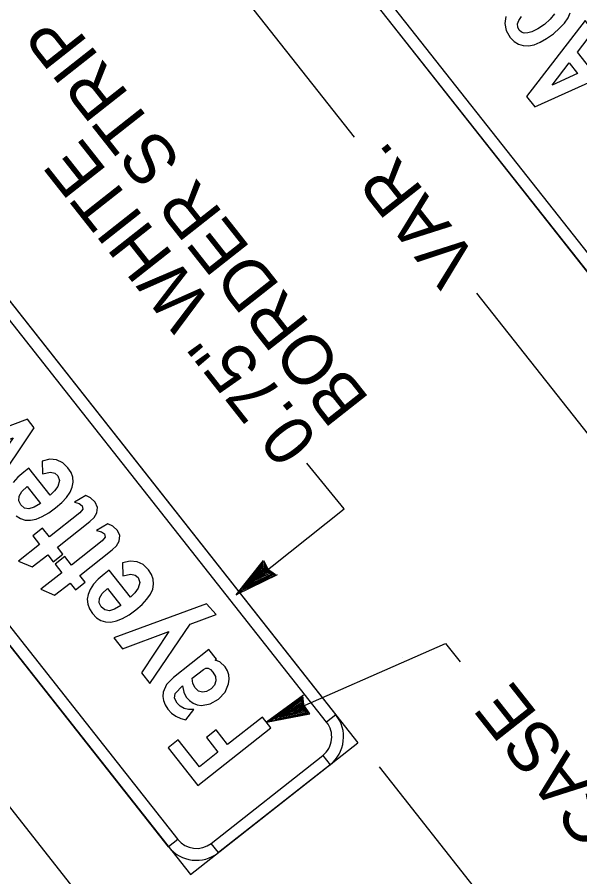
# Model space of a CAD drawing. Extents: x 672126 to 673696, y 1673540 to 1674900.
# Drawn here: x 672259.8 to 672307.3, y 1674609.9 to 1674682.5 of the extents above; entities that cross this region are included whole.
import ezdxf

# ---------------------------------------------------------------- set-up
doc = ezdxf.new("R2010")
doc.units = 0
for name, color, linetype in [('C-ANNO-SYMB', 7, 'Continuous'), ('Level 1', 7, 'Continuous'), ('V-SIGNAL-LOOP', 7, 'Continuous')]:
    doc.layers.add(name, color=color, linetype=linetype)

msp = doc.modelspace()

# ---------------------------------------------------------------- linework, layer by layer
at = {"layer": 'C-ANNO-SYMB'}
for p, q in [((672275.262, 1674702.456), (672319.838, 1674645.914)), ((672247.706, 1674673.092), (672288.567, 1674621.261)), ((672233.571, 1674661.948), (672274.431, 1674610.117)), ((672286.71, 1674623.617), (672285.924, 1674622.998)), ((672274.431, 1674610.117), (672288.567, 1674621.261)), ((672285.592, 1674620.189), (672286.211, 1674619.404)), ((672273.359, 1674613.092), (672272.574, 1674612.473)), ((672276.787, 1674611.975), (672276.168, 1674612.76))]:
    msp.add_line(p, q, dxfattribs=at)
for points in [[(672277.905, 1674700.719), (672318.766, 1674648.889), (672317.98, 1674648.27), (672277.12, 1674700.1), (672277.905, 1674700.719), (672277.905, 1674700.719)], [(672285.924, 1674622.998), (672248.778, 1674670.117), (672249.564, 1674670.736), (672286.71, 1674623.617), (672285.924, 1674622.998), (672285.924, 1674622.998)], [(672236.213, 1674660.211), (672273.359, 1674613.092), (672272.574, 1674612.473), (672235.428, 1674659.592), (672236.213, 1674660.211), (672236.213, 1674660.211)], [(672257.802, 1674642.767), (672261.237, 1674647.852), (672260.664, 1674648.579), (672254.912, 1674646.433), (672255.696, 1674645.551), (672259.462, 1674647.025), (672257.166, 1674643.686)], [(672264.626, 1674641.585), (672265.042, 1674641.455), (672265.278, 1674641.283), (672265.345, 1674640.996), (672265.1, 1674640.689), (672262.516, 1674638.652), (672261.937, 1674639.386), (672261.117, 1674638.74), (672261.696, 1674638.006), (672259.918, 1674636.604), (672261.08, 1674636.109), (672262.382, 1674637.136), (672262.842, 1674636.553), (672263.662, 1674637.199), (672263.202, 1674637.782), (672265.933, 1674639.935), (672266.301, 1674640.292), (672266.526, 1674640.675), (672266.582, 1674641.142), (672266.385, 1674641.57), (672266.004, 1674641.941), (672265.584, 1674642.13)], [(672266.508, 1674639.198), (672266.924, 1674639.067), (672267.16, 1674638.895), (672267.227, 1674638.609), (672266.982, 1674638.302), (672264.398, 1674636.265), (672263.819, 1674636.999), (672263, 1674636.353), (672263.578, 1674635.619), (672261.8, 1674634.217), (672262.962, 1674633.722), (672264.264, 1674634.748), (672264.724, 1674634.165), (672265.544, 1674634.812), (672265.084, 1674635.394), (672267.815, 1674637.547), (672268.183, 1674637.904), (672268.408, 1674638.287), (672268.464, 1674638.754), (672268.267, 1674639.183), (672267.886, 1674639.553), (672267.466, 1674639.743)], [(672276.595, 1674632.098), (672275.794, 1674632.989), (672267.961, 1674630.13), (672268.701, 1674629.191), (672272.617, 1674630.656), (672270.294, 1674627.171), (672270.999, 1674626.277), (672274.405, 1674631.287)], [(672281.214, 1674622.512), (672280.498, 1674623.42), (672277.564, 1674621.108), (672276.59, 1674622.344), (672275.778, 1674621.705), (672276.753, 1674620.468), (672275.182, 1674619.23), (672273.4, 1674621.491), (672272.554, 1674620.824), (672275.052, 1674617.655)], [(672276.168, 1674612.76), (672285.592, 1674620.189), (672286.211, 1674619.404), (672276.787, 1674611.975), (672276.168, 1674612.76), (672276.168, 1674612.76)]]:
    msp.add_lwpolyline(points, close=True, dxfattribs=at)
for points in [[(672301.055, 1674682.604), (672300.962, 1674682.007), (672301.088, 1674681.405), (672301.42, 1674680.832), (672301.751, 1674680.489), (672302.116, 1674680.26), (672302.519, 1674680.137), (672302.955, 1674680.123), (672303.432, 1674680.217), (672303.94, 1674680.419), (672304.487, 1674680.731), (672305.069, 1674681.15), (672305.591, 1674681.602), (672306.002, 1674682.045), (672306.303, 1674682.481), (672306.489, 1674682.909)], [(672305.163, 1674682.816), (672304.8, 1674682.376), (672304.305, 1674681.937), (672303.764, 1674681.563), (672303.245, 1674681.312), (672302.903, 1674681.211), (672302.61, 1674681.198), (672302.373, 1674681.27), (672302.183, 1674681.433), (672302.05, 1674681.69), (672302.037, 1674681.967), (672302.146, 1674682.268), (672302.371, 1674682.588)], [(672310.87, 1674678.287), (672310.165, 1674679.181), (672308.14, 1674678.261), (672307.092, 1674679.59), (672308.445, 1674681.364), (672307.735, 1674682.264), (672302.798, 1674675.853), (672303.485, 1674674.983), (672310.87, 1674678.287)], [(672307.092, 1674677.787), (672304.96, 1674676.811), (672306.387, 1674678.682), (672307.092, 1674677.787)], [(672259.709, 1674640.431), (672260.076, 1674640.197), (672260.481, 1674640.072), (672260.919, 1674640.059), (672261.399, 1674640.154), (672261.911, 1674640.358), (672262.46, 1674640.672), (672263.046, 1674641.094), (672263.564, 1674641.542), (672263.972, 1674641.983), (672264.27, 1674642.418), (672264.454, 1674642.844), (672264.532, 1674643.263), (672264.495, 1674643.677), (672264.348, 1674644.085), (672264.088, 1674644.483), (672263.643, 1674644.912), (672263.132, 1674645.15), (672262.556, 1674645.198), (672261.91, 1674645.053), (672261.947, 1674643.973), (672262.621, 1674644.102), (672262.977, 1674644.029), (672263.243, 1674643.817), (672263.38, 1674643.414), (672263.224, 1674642.914), (672262.957, 1674642.53), (672262.589, 1674642.163)], [(672262.589, 1674642.163), (672260.785, 1674644.45), (672260.36, 1674644.115), (672259.86, 1674643.679), (672259.463, 1674643.246)], [(672261.762, 1674641.471), (672261.245, 1674641.149), (672260.795, 1674641.021), (672260.414, 1674641.085), (672260.102, 1674641.341), (672259.934, 1674641.694), (672259.965, 1674642.075), (672260.2, 1674642.474), (672260.636, 1674642.9), (672261.762, 1674641.471)], [(672269.374, 1674633.555), (672267.571, 1674635.843), (672267.146, 1674635.508), (672266.646, 1674635.072), (672266.248, 1674634.639), (672265.963, 1674634.213), (672265.784, 1674633.793), (672265.717, 1674633.376), (672265.756, 1674632.965), (672265.907, 1674632.561), (672266.161, 1674632.164), (672266.494, 1674631.823), (672266.861, 1674631.589), (672267.267, 1674631.465), (672267.705, 1674631.452), (672268.185, 1674631.547), (672268.696, 1674631.751), (672269.245, 1674632.065), (672269.831, 1674632.487), (672270.349, 1674632.935), (672270.758, 1674633.376), (672271.056, 1674633.811), (672271.24, 1674634.237), (672271.317, 1674634.656), (672271.28, 1674635.07), (672271.133, 1674635.478), (672270.873, 1674635.876), (672270.428, 1674636.305), (672269.918, 1674636.543), (672269.341, 1674636.591), (672268.696, 1674636.446), (672268.733, 1674635.366), (672269.406, 1674635.495), (672269.763, 1674635.422), (672270.028, 1674635.21), (672270.166, 1674634.807), (672270.009, 1674634.307), (672269.742, 1674633.923), (672269.374, 1674633.555)], [(672268.548, 1674632.864), (672268.03, 1674632.542), (672267.581, 1674632.414), (672267.2, 1674632.478), (672266.887, 1674632.734), (672266.719, 1674633.087), (672266.75, 1674633.468), (672266.986, 1674633.867), (672267.421, 1674634.293), (672268.548, 1674632.864)], [(672276.627, 1674628.33), (672275.99, 1674629.139), (672272.99, 1674626.774), (672272.412, 1674626.18), (672272.115, 1674625.539), (672272.084, 1674625.174), (672272.14, 1674624.814), (672272.287, 1674624.452), (672272.521, 1674624.096), (672272.842, 1674623.755), (672273.203, 1674623.492), (672273.608, 1674623.305), (672274.049, 1674623.194), (672274.704, 1674624.072), (672274.275, 1674624.074), (672273.893, 1674624.162), (672273.57, 1674624.339), (672273.3, 1674624.599), (672273.081, 1674625.036), (672273.147, 1674625.422), (672273.763, 1674626.073), (672273.857, 1674625.529), (672274.072, 1674625.11), (672274.354, 1674624.815), (672274.662, 1674624.603), (672275.005, 1674624.469), (672275.373, 1674624.413), (672276.099, 1674624.536), (672276.805, 1674624.945), (672277.351, 1674625.531), (672277.649, 1674626.235), (672277.705, 1674626.625), (672277.672, 1674626.993), (672277.555, 1674627.339), (672277.35, 1674627.661), (672276.919, 1674628.083), (672276.503, 1674628.233), (672276.627, 1674628.33)], [(672274.573, 1674626.711), (672275.521, 1674627.459), (672275.716, 1674627.557), (672275.914, 1674627.551), (672276.118, 1674627.439), (672276.325, 1674627.223), (672276.536, 1674626.851), (672276.575, 1674626.475), (672276.453, 1674626.122), (672276.169, 1674625.814), (672275.791, 1674625.587), (672275.441, 1674625.523), (672275.121, 1674625.625), (672274.827, 1674625.893), (672274.634, 1674626.263), (672274.573, 1674626.711)]]:
    msp.add_lwpolyline(points, dxfattribs=at)
for centre, radius, start, end in [((672284.354, 1674621.76), 3, 308.25039, 38.2506), ((672284.354, 1674621.76), 2, 308.25039, 38.2506), ((672274.93, 1674614.331), 2, 218.25075, 308.25039), ((672274.93, 1674614.331), 3, 218.25075, 308.25039)]:
    msp.add_arc(centre, radius, start, end, dxfattribs=at)
at = {"layer": 'Level 1'}
for p, q in [((672288.283, 1674672.401), (672272.326, 1674692.642)), ((672313.221, 1674640.698), (672298.606, 1674659.236)), ((672278.286, 1674633.743), (672280.606, 1674636.653)), ((672278.504, 1674633.979), (672280.588, 1674636.505)), ((672278.855, 1674634.255), (672280.585, 1674636.336)), ((672279.074, 1674634.355), (672280.628, 1674636.071)), ((672279.145, 1674634.479), (672280.587, 1674636.205)), ((672280.585, 1674636.336), (672280.723, 1674636.076)), ((672280.587, 1674636.205), (672281.268, 1674635.507)), ((672280.588, 1674636.505), (672280.929, 1674635.94)), ((672280.606, 1674636.653), (672280.998, 1674635.894)), ((672280.628, 1674636.071), (672281.089, 1674635.565)), ((672280.723, 1674636.076), (672281.268, 1674635.507)), ((672281.747, 1674635.449), (672278.286, 1674633.743)), ((672281.389, 1674635.435), (672278.546, 1674634.011)), ((672281.555, 1674635.397), (672278.707, 1674634.103)), ((672281.268, 1674635.507), (672279.074, 1674634.355)), ((672281.268, 1674635.507), (672279.145, 1674634.479)), ((672279.579, 1674634.818), (672280.573, 1674635.927)), ((672281.089, 1674635.565), (672279.579, 1674634.818)), ((672279.966, 1674635.088), (672280.537, 1674635.8)), ((672280.926, 1674635.605), (672279.966, 1674635.088)), ((672280.631, 1674635.94), (672280.126, 1674635.181)), ((672280.302, 1674635.383), (672280.567, 1674635.723)), ((672280.819, 1674635.654), (672280.302, 1674635.383)), ((672280.537, 1674635.8), (672280.819, 1674635.654)), ((672280.567, 1674635.723), (672280.65, 1674635.658)), ((672280.573, 1674635.927), (672280.926, 1674635.605)), ((672281.007, 1674635.669), (672280.631, 1674635.94)), ((672280.65, 1674635.658), (672281.007, 1674635.669)), ((672280.929, 1674635.94), (672281.6, 1674635.467)), ((672280.998, 1674635.894), (672281.24, 1674635.584)), ((672281.24, 1674635.584), (672281.555, 1674635.397)), ((672281.6, 1674635.467), (672281.381, 1674635.53)), ((672281.381, 1674635.53), (672281.389, 1674635.435)), ((672280.126, 1674635.181), (672279.872, 1674635.081)), ((672283.973, 1674625.266), (672280.853, 1674622.996)), ((672283.837, 1674625.12), (672281.368, 1674623.201)), ((672283.857, 1674624.755), (672283.837, 1674625.12)), ((672283.921, 1674625.127), (672283.875, 1674624.904)), ((672284.027, 1674624.314), (672283.921, 1674625.127)), ((672283.794, 1674624.956), (672281.211, 1674623.102)), ((672283.802, 1674624.815), (672281.761, 1674623.409)), ((672283.802, 1674624.815), (672281.904, 1674623.415)), ((672283.77, 1674624.629), (672282.406, 1674623.641)), ((672283.729, 1674624.467), (672282.825, 1674623.858)), ((672283.723, 1674624.349), (672283.243, 1674624.018)), ((672283.648, 1674624.198), (672283.824, 1674624.509)), ((672283.721, 1674624.032), (672283.723, 1674624.349)), ((672283.85, 1674624.004), (672283.729, 1674624.467)), ((672284.004, 1674623.986), (672283.77, 1674624.629)), ((672283.875, 1674624.904), (672283.794, 1674624.956)), ((672284.052, 1674624.068), (672283.802, 1674624.815)), ((672284.103, 1674623.887), (672283.802, 1674624.815)), ((672283.824, 1674624.509), (672283.889, 1674624.05)), ((672284.019, 1674624.397), (672283.857, 1674624.755)), ((672284.509, 1674623.696), (672284.019, 1674624.397)), ((672280.853, 1674622.996), (672284.509, 1674623.696)), ((672281.164, 1674623.079), (672284.369, 1674623.749)), ((672281.334, 1674623.271), (672282.082, 1674623.781)), ((672281.571, 1674623.262), (672284.218, 1674623.825)), ((672282.082, 1674623.781), (672281.571, 1674623.262)), ((672281.761, 1674623.409), (672284.004, 1674623.986)), ((672281.904, 1674623.415), (672284.103, 1674623.887)), ((672282.299, 1674623.62), (672282.686, 1674623.909)), ((672282.775, 1674623.778), (672282.299, 1674623.62)), ((672282.406, 1674623.641), (672283.85, 1674624.004)), ((672282.982, 1674623.956), (672282.775, 1674623.778)), ((672282.825, 1674623.858), (672283.721, 1674624.032)), ((672283.889, 1674624.05), (672282.982, 1674623.956)), ((672283.243, 1674624.018), (672283.667, 1674624.095)), ((672283.667, 1674624.095), (672283.648, 1674624.198)), ((672284.369, 1674623.749), (672284.027, 1674624.314)), ((672284.218, 1674623.825), (672284.052, 1674624.068)), ((672267.807, 1674604.895), (672253.192, 1674623.434)), ((672281.368, 1674623.201), (672281.164, 1674623.079)), ((672281.211, 1674623.102), (672281.334, 1674623.271)), ((672290.346, 1674619.218), (672299.175, 1674608.019))]:
    msp.add_line(p, q, dxfattribs=at)
for points in [[(672278.286, 1674633.743), (672287.399, 1674641.004), (672284.261, 1674644.86)], [(672280.853, 1674622.996), (672295.961, 1674629.633), (672297.184, 1674628.083)]]:
    msp.add_lwpolyline(points, dxfattribs=at)
at = {"layer": 'V-SIGNAL-LOOP'}
msp.add_lwpolyline([(672292.36, 1674628.454), (672292.36, 1674628.454), (672292.36, 1674628.454)], dxfattribs=at)

# ---------------------------------------------------------------- texts
at = {"layer": 'Level 1'}
for s, p in [('BORDER STRIP', (672289.626, 1674650.257)), ('0.75" WHITE ', (672285.332, 1674646.872)), ('VAR.', (672298.867, 1674661.956)), ('8" UPPERCASE', (672327.105, 1674594.135))]:
    msp.add_text(s, height=4.2, rotation=128.25054, dxfattribs=at).set_placement(p)

doc.saveas('drawing.dxf')
